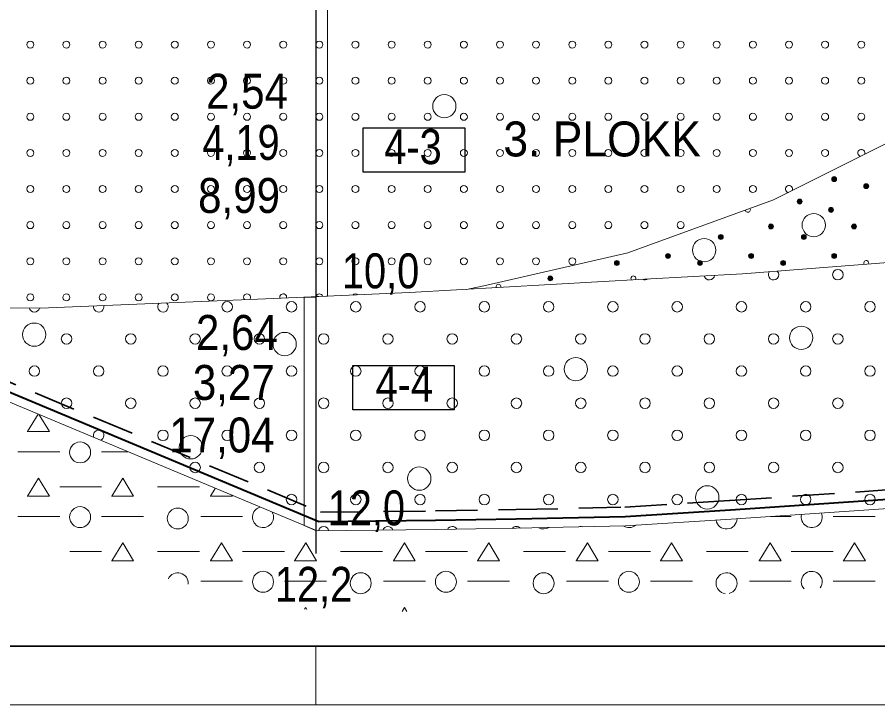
# Model space of a CAD drawing. Extents: x 640104 to 640970, y 6442278 to 6442689.
# Drawn here: x 640245.1 to 640319, y 6442488 to 6442547 of the extents above; entities that cross this region are included whole.
import ezdxf
from ezdxf.enums import TextEntityAlignment as Align

# ---------------------------------------------------------------- set-up
doc = ezdxf.new("R2010")
doc.units = 0
doc.header["$LTSCALE"] = 1.2
doc.linetypes.add('MEDIUM_DASHED', pattern=[4.5, 3, -1.5])
for name, color, linetype, lineweight in [('30', 7, 'Continuous', 13), ('31', 7, 'Continuous', 13), ('32', 7, 'Continuous', 25), ('33', 7, 'Continuous', 13), ('35', 7, 'Continuous', 35), ('42', 7, 'Continuous', 13), ('43', 7, 'Continuous', 13), ('44', 7, 'Continuous', 13), ('46', 7, 'Continuous', 13), ('47', 7, 'Continuous', 13)]:
    doc.layers.add(name, color=color, linetype=linetype, lineweight=lineweight)

msp = doc.modelspace()

# ---------------------------------------------------------------- hatches: boundary and pattern name
at = {"layer": '44'}
for points in [[(640315.439, 6442533.125, 1), (640315.019, 6442533.125, 1)], [(640318.187, 6442532.519, 1), (640317.767, 6442532.519, 1)], [(640312.473, 6442531.197, 1), (640312.053, 6442531.197, 1)], [(640315.165, 6442530.482, 1), (640314.745, 6442530.482, 1)], [(640310.01, 6442529.063, 1), (640309.59, 6442529.063, 1)], [(640317.143, 6442529.063, 1), (640316.723, 6442529.063, 1)], [(640305.704, 6442528.155, 1), (640305.284, 6442528.155, 1)], [(640312.837, 6442528.155, 1), (640312.417, 6442528.155, 1)], [(640301.173, 6442526.529, 1), (640300.753, 6442526.529, 1)], [(640308.306, 6442526.529, 1), (640307.886, 6442526.529, 1)], [(640315.439, 6442526.529, 1), (640315.019, 6442526.529, 1)], [(640296.788, 6442525.923, 1), (640296.368, 6442525.923, 1)], [(640303.921, 6442525.923, 1), (640303.501, 6442525.923, 1)], [(640311.054, 6442525.923, 1), (640310.634, 6442525.923, 1)], [(640291.074, 6442524.601, 1), (640290.654, 6442524.601, 1)]]:
    msp.add_hatch(color=256, dxfattribs=at).paths.add_polyline_path(points)

# ---------------------------------------------------------------- linework, layer by layer
at = {"layer": '30'}
msp.add_line((640270.76, 6442493), (640270.76, 6442488), dxfattribs=at)
at = {"layer": '31'}
for p, q in [((640107.01, 6442493.07), (640418.42, 6442493.07)), ((640107.01, 6442493), (640418.42, 6442493)), ((640107.01, 6442488), (640418.42, 6442488))]:
    msp.add_line(p, q, dxfattribs=at)
for points in [[(640283.68, 6442523.66), (640285.43, 6442524.03), (640297.52, 6442526.8), (640310.03, 6442531.34), (640323.29, 6442537.98), (640334.86, 6442544.42), (640343.76, 6442550.3), (640349.45, 6442554.85), (640357.08, 6442560.74), (640362.52, 6442565.74), (640369.51, 6442571.79), (640374.98, 6442577.56), (640379.02, 6442582.52), (640385.32, 6442590.78), (640390.41, 6442598.26), (640395.12, 6442604.77), (640397.49, 6442607.37), (640400.85, 6442610.03)], [(640224.72, 6442522.23), (640247.13, 6442522.05), (640267.13, 6442522.88), (640278.78, 6442523.38), (640298.96, 6442524.54), (640307.35, 6442525), (640322.43, 6442526.17), (640329.85, 6442527.49), (640338.89, 6442529.33), (640344.87, 6442530.55), (640353.66, 6442533.23), (640361.47, 6442536.65), (640368.18, 6442539.82), (640375.75, 6442544.7), (640385.64, 6442551.91), (640392.23, 6442556.06), (640395.16, 6442557.52), (640398.21, 6442558.74), (640401.26, 6442559.84), (640404.41, 6442560.91), (640412.75, 6442561.86), (640417.91, 6442562.22), (640418.42, 6442562.2)], [(640136.43, 6442546.57), (640165.21, 6442545.08), (640170.39, 6442544.98), (640270.85, 6442502.92), (640281.03, 6442503.04), (640287.95, 6442503.15), (640297.33, 6442503.37), (640306.38, 6442503.93), (640319.46, 6442504.83), (640339.78, 6442506.39), (640353.27, 6442507.39), (640379.6, 6442511.07), (640396.05, 6442513.09), (640404.66, 6442514), (640412.22, 6442514.76), (640418.42, 6442515.39)]]:
    msp.add_lwpolyline(points, dxfattribs=at)
at = {"layer": '32'}
msp.add_line((640270.76, 6442623), (640270.76, 6442501), dxfattribs=at)
at = {"layer": '33'}
for points in [[(640271.76, 6442523.08), (640271.76, 6442548), (640270.76, 6442548), (640270.76, 6442523.04)], [(640269.76, 6442522.99), (640269.76, 6442503.38), (640270.66, 6442503), (640270.76, 6442503), (640270.76, 6442523), (640269.93, 6442523)]]:
    msp.add_lwpolyline(points, close=True, dxfattribs=at)
at = {"layer": '33', "lineweight": 25}
for points in [[(640274.82, 6442537.53), (640283.53, 6442537.53), (640283.53, 6442533.73), (640274.82, 6442533.73)], [(640273.92, 6442517.13), (640282.63, 6442517.13), (640282.63, 6442513.33), (640273.92, 6442513.33)]]:
    msp.add_lwpolyline(points, close=True, dxfattribs=at)
at = {"layer": '35', "linetype": 'MEDIUM_DASHED'}
msp.add_lwpolyline([(640171.96, 6442546.06), (640271.16, 6442504.53), (640281.01, 6442504.64), (640287.92, 6442504.75), (640297.26, 6442504.97), (640306.27, 6442505.53), (640319.35, 6442506.42), (640339.66, 6442507.99), (640353.1, 6442508.98), (640379.39, 6442512.65), (640395.87, 6442514.68), (640403.06, 6442515.44)], dxfattribs=at)
at = {"layer": '35', "lineweight": 40}
msp.add_lwpolyline([(640171.16, 6442545.53), (640271, 6442503.73), (640281.02, 6442503.84), (640287.94, 6442503.95), (640297.3, 6442504.17), (640306.32, 6442504.73), (640319.41, 6442505.62), (640339.72, 6442507.19), (640353.18, 6442508.19), (640379.49, 6442511.86), (640395.96, 6442513.88), (640403.86, 6442514.72)], dxfattribs=at)
at = {"layer": '42'}
for centre in [(640315.544, 6442524.92), (640263.147, 6442522.162), (640268.663, 6442522.162), (640274.178, 6442522.162), (640279.693, 6442522.162), (640285.209, 6442522.162), (640290.724, 6442522.162), (640296.24, 6442522.162), (640301.755, 6442522.162), (640307.271, 6442522.162), (640312.786, 6442522.162), (640318.301, 6442522.162), (640249.359, 6442519.404), (640254.874, 6442519.404), (640260.389, 6442519.404), (640265.905, 6442519.404), (640271.42, 6442519.404), (640276.936, 6442519.404), (640282.451, 6442519.404), (640287.967, 6442519.404), (640293.482, 6442519.404), (640298.997, 6442519.404), (640304.513, 6442519.404), (640310.028, 6442519.404), (640315.544, 6442519.404), (640246.601, 6442516.647), (640252.116, 6442516.647), (640257.632, 6442516.647), (640263.147, 6442516.647), (640268.663, 6442516.647), (640274.178, 6442516.647), (640279.693, 6442516.647), (640285.209, 6442516.647), (640290.724, 6442516.647), (640296.24, 6442516.647), (640301.755, 6442516.647), (640307.271, 6442516.647), (640312.786, 6442516.647), (640318.301, 6442516.647), (640249.359, 6442513.889), (640254.874, 6442513.889), (640260.389, 6442513.889), (640265.905, 6442513.889), (640271.42, 6442513.889), (640276.936, 6442513.889), (640282.451, 6442513.889), (640287.967, 6442513.889), (640293.482, 6442513.889), (640298.997, 6442513.889), (640304.513, 6442513.889), (640310.028, 6442513.889), (640315.544, 6442513.889), (640257.632, 6442511.131), (640263.147, 6442511.131), (640268.663, 6442511.131), (640274.178, 6442511.131), (640279.693, 6442511.131), (640285.209, 6442511.131), (640290.724, 6442511.131), (640296.24, 6442511.131), (640301.755, 6442511.131), (640307.271, 6442511.131), (640312.786, 6442511.131), (640318.301, 6442511.131), (640260.389, 6442508.374), (640265.905, 6442508.374), (640271.42, 6442508.374), (640276.936, 6442508.374), (640282.451, 6442508.374), (640287.967, 6442508.374), (640293.482, 6442508.374), (640298.997, 6442508.374), (640304.513, 6442508.374), (640310.028, 6442508.374), (640315.544, 6442508.374), (640268.663, 6442505.616), (640274.178, 6442505.616), (640279.693, 6442505.616), (640285.209, 6442505.616), (640290.724, 6442505.616), (640296.24, 6442505.616), (640301.755, 6442505.616), (640307.271, 6442505.616), (640312.786, 6442505.616), (640318.301, 6442505.616)]:
    msp.add_circle(centre, 0.45, dxfattribs=at)
for centre, start, end in [((640310.028, 6442524.92), 144.28306, 44.54039), ((640298.997, 6442524.92), 239.27292, 307.13568), ((640304.513, 6442524.92), 192.23369, 354.04276), ((640246.601, 6442522.162), 193.37807, 345.67679), ((640252.116, 6442522.162), 170.14064, 14.62174), ((640257.632, 6442522.162), 136.22376, 48.53863), ((640252.116, 6442511.131), 288.70447, 205.86033), ((640271.42, 6442502.858), 9.85513, 171.43858), ((640276.936, 6442502.858), 18.00801, 163.2857), ((640282.451, 6442502.858), 27.79631, 154.05178), ((640287.967, 6442502.858), 41.88958, 140.40784), ((640293.482, 6442502.858), 71.67364, 111.05422)]:
    msp.add_arc(centre, 0.45, start, end, dxfattribs=at)
at = {"layer": '43'}
for centre in [(640246.249, 6442544.673), (640249.349, 6442544.673), (640252.449, 6442544.673), (640255.549, 6442544.673), (640258.649, 6442544.673), (640261.749, 6442544.673), (640264.849, 6442544.673), (640267.949, 6442544.673), (640271.049, 6442544.673), (640274.149, 6442544.673), (640277.249, 6442544.673), (640280.349, 6442544.673), (640283.449, 6442544.673), (640286.549, 6442544.673), (640289.649, 6442544.673), (640292.749, 6442544.673), (640295.849, 6442544.673), (640298.949, 6442544.673), (640302.049, 6442544.673), (640305.149, 6442544.673), (640308.249, 6442544.673), (640311.349, 6442544.673), (640314.449, 6442544.673), (640317.549, 6442544.673), (640246.249, 6442541.573), (640249.349, 6442541.573), (640252.449, 6442541.573), (640255.549, 6442541.573), (640258.649, 6442541.573), (640261.749, 6442541.573), (640264.849, 6442541.573), (640267.949, 6442541.573), (640271.049, 6442541.573), (640274.149, 6442541.573), (640277.249, 6442541.573), (640280.349, 6442541.573), (640283.449, 6442541.573), (640286.549, 6442541.573), (640289.649, 6442541.573), (640292.749, 6442541.573), (640295.849, 6442541.573), (640298.949, 6442541.573), (640302.049, 6442541.573), (640305.149, 6442541.573), (640308.249, 6442541.573), (640311.349, 6442541.573), (640314.449, 6442541.573), (640317.549, 6442541.573), (640246.249, 6442538.473), (640249.349, 6442538.473), (640252.449, 6442538.473), (640255.549, 6442538.473), (640258.649, 6442538.473), (640261.749, 6442538.473), (640264.849, 6442538.473), (640267.949, 6442538.473), (640271.049, 6442538.473), (640274.149, 6442538.473), (640277.249, 6442538.473), (640280.349, 6442538.473), (640283.449, 6442538.473), (640286.549, 6442538.473), (640289.649, 6442538.473), (640292.749, 6442538.473), (640295.849, 6442538.473), (640298.949, 6442538.473), (640302.049, 6442538.473), (640305.149, 6442538.473), (640308.249, 6442538.473), (640311.349, 6442538.473), (640314.449, 6442538.473), (640317.549, 6442538.473), (640246.249, 6442535.373), (640249.349, 6442535.373), (640252.449, 6442535.373), (640255.549, 6442535.373), (640258.649, 6442535.373), (640261.749, 6442535.373), (640264.849, 6442535.373), (640267.949, 6442535.373), (640271.049, 6442535.373), (640274.149, 6442535.373), (640277.249, 6442535.373), (640280.349, 6442535.373), (640283.449, 6442535.373), (640286.549, 6442535.373), (640289.649, 6442535.373), (640292.749, 6442535.373), (640295.849, 6442535.373), (640298.949, 6442535.373), (640302.049, 6442535.373), (640305.149, 6442535.373), (640308.249, 6442535.373), (640311.349, 6442535.373), (640314.449, 6442535.373), (640246.249, 6442532.273), (640249.349, 6442532.273), (640252.449, 6442532.273), (640255.549, 6442532.273), (640258.649, 6442532.273), (640261.749, 6442532.273), (640264.849, 6442532.273), (640267.949, 6442532.273), (640271.049, 6442532.273), (640274.149, 6442532.273), (640277.249, 6442532.273), (640280.349, 6442532.273), (640283.449, 6442532.273), (640286.549, 6442532.273), (640289.649, 6442532.273), (640292.749, 6442532.273), (640295.849, 6442532.273), (640298.949, 6442532.273), (640302.049, 6442532.273), (640305.149, 6442532.273), (640308.249, 6442532.273), (640246.249, 6442529.173), (640249.349, 6442529.173), (640252.449, 6442529.173), (640255.549, 6442529.173), (640258.649, 6442529.173), (640261.749, 6442529.173), (640264.849, 6442529.173), (640267.949, 6442529.173), (640271.049, 6442529.173), (640274.149, 6442529.173), (640277.249, 6442529.173), (640280.349, 6442529.173), (640283.449, 6442529.173), (640286.549, 6442529.173), (640289.649, 6442529.173), (640292.749, 6442529.173), (640295.849, 6442529.173), (640298.949, 6442529.173), (640302.049, 6442529.173), (640246.249, 6442526.073), (640249.349, 6442526.073), (640252.449, 6442526.073), (640255.549, 6442526.073), (640258.649, 6442526.073), (640261.749, 6442526.073), (640264.849, 6442526.073), (640267.949, 6442526.073), (640271.049, 6442526.073), (640274.149, 6442526.073), (640277.249, 6442526.073), (640280.349, 6442526.073), (640283.449, 6442526.073), (640286.549, 6442526.073), (640289.649, 6442526.073), (640292.749, 6442526.073), (640246.249, 6442522.973), (640249.349, 6442522.973), (640252.449, 6442522.973), (640255.549, 6442522.973), (640258.649, 6442522.973), (640261.749, 6442522.973)]:
    msp.add_circle(centre, 0.3, dxfattribs=at)
for centre, start, end in [((640317.549, 6442535.373), 333.52941, 259.60069), ((640311.349, 6442532.273), 333.52941, 259.60069), ((640264.849, 6442522.973), 324.16538, 220.597), ((640267.949, 6442522.973), 351.67862, 193.19468), ((640271.049, 6442522.973), 17.07144, 167.80185), ((640274.149, 6442522.973), 46.22336, 138.64994)]:
    msp.add_arc(centre, 0.3, start, end, dxfattribs=at)
at = {"layer": '44'}
for centre in [(640315.229, 6442533.125), (640317.977, 6442532.519), (640312.263, 6442531.197), (640314.955, 6442530.482), (640309.8, 6442529.063), (640316.933, 6442529.063), (640305.494, 6442528.155), (640312.627, 6442528.155), (640300.963, 6442526.529), (640308.096, 6442526.529), (640315.229, 6442526.529), (640296.578, 6442525.923), (640303.711, 6442525.923), (640310.844, 6442525.923), (640290.864, 6442524.601)]:
    msp.add_circle(centre, 0.21, dxfattribs=at)
for centre, start, end in [((640307.822, 6442530.482), 184.23112, 35.7351), ((640317.977, 6442525.923), 336.24488, 212.57856), ((640297.997, 6442524.601), 330.86934, 215.74711), ((640286.423, 6442523.886), 345.01586, 201.60058)]:
    msp.add_arc(centre, 0.21, start, end, dxfattribs=at)
at = {"layer": '46'}
for p, q in [((640248.77, 6442509.72), (640245.17, 6442509.72)), ((640254.63, 6442509.71), (640252.37, 6442509.71)), ((640252.37, 6442506.72), (640248.77, 6442506.72)), ((640260.77, 6442506.72), (640257.17, 6442506.72)), ((640248.77, 6442504.16), (640245.17, 6442504.16)), ((640255.97, 6442504.16), (640252.37, 6442504.16)), ((640264.47, 6442504.16), (640260.87, 6442504.16)), ((640311.55, 6442504.16), (640309.76, 6442504.16)), ((640318.75, 6442504.16), (640315.15, 6442504.16)), ((640252.37, 6442501.16), (640249.65, 6442501.16)), ((640260.77, 6442501.17), (640257.17, 6442501.17)), ((640268.07, 6442501.16), (640264.47, 6442501.16)), ((640276.47, 6442501.17), (640272.87, 6442501.17)), ((640283.76, 6442501.16), (640280.16, 6442501.16)), ((640292.16, 6442501.17), (640288.56, 6442501.17)), ((640299.46, 6442501.16), (640295.86, 6442501.16)), ((640307.86, 6442501.17), (640304.26, 6442501.17)), ((640315.15, 6442501.16), (640311.55, 6442501.16)), ((640264.47, 6442498.61), (640260.87, 6442498.61)), ((640271.67, 6442498.6), (640268.07, 6442498.6)), ((640280.16, 6442498.61), (640276.56, 6442498.61)), ((640287.36, 6442498.6), (640283.76, 6442498.6)), ((640295.86, 6442498.61), (640292.26, 6442498.61)), ((640303.06, 6442498.6), (640299.46, 6442498.6)), ((640311.55, 6442498.61), (640307.95, 6442498.61)), ((640318.75, 6442498.6), (640315.15, 6442498.6))]:
    msp.add_line(p, q, dxfattribs=at)
for points in [[(640246.01, 6442511.44), (640246.02, 6442511.47), (640246.93, 6442512.94)], [(640247.02, 6442512.9), (640247.89, 6442511.46), (640246.09, 6442511.47)], [(640246.01, 6442505.89), (640246.02, 6442505.91), (640246.96, 6442507.44), (640247.89, 6442505.9), (640246.09, 6442505.91)], [(640253.23, 6442505.89), (640253.24, 6442505.91), (640254.18, 6442507.44), (640255.11, 6442505.9), (640253.31, 6442505.91)], [(640261.71, 6442505.89), (640261.71, 6442505.91), (640262.12, 6442506.58)], [(640263.54, 6442505.98), (640263.59, 6442505.9), (640261.79, 6442505.91)], [(640253.23, 6442500.34), (640253.24, 6442500.36), (640254.18, 6442501.89), (640255.11, 6442500.35), (640253.31, 6442500.36)], [(640261.71, 6442500.34), (640261.71, 6442500.36), (640262.66, 6442501.89), (640263.59, 6442500.35), (640261.79, 6442500.36)], [(640268.93, 6442500.34), (640268.93, 6442500.36), (640269.88, 6442501.89), (640270.81, 6442500.35), (640269.01, 6442500.36)], [(640277.4, 6442500.34), (640277.41, 6442500.36), (640278.35, 6442501.89), (640279.28, 6442500.35), (640277.48, 6442500.36)], [(640284.62, 6442500.34), (640284.63, 6442500.36), (640285.58, 6442501.89), (640286.51, 6442500.35), (640284.71, 6442500.36)], [(640293.1, 6442500.34), (640293.1, 6442500.36), (640294.05, 6442501.89), (640294.98, 6442500.35), (640293.18, 6442500.36)], [(640300.32, 6442500.34), (640300.32, 6442500.36), (640301.27, 6442501.89), (640302.2, 6442500.35), (640300.4, 6442500.36)], [(640308.79, 6442500.34), (640308.8, 6442500.36), (640309.74, 6442501.89), (640310.67, 6442500.35), (640308.87, 6442500.36)], [(640316.01, 6442500.34), (640316.02, 6442500.36), (640316.97, 6442501.89), (640317.9, 6442500.35), (640316.1, 6442500.36)], [(640269.79, 6442496.2), (640269.88, 6442496.34), (640269.97, 6442496.19)], [(640278.16, 6442496.02), (640278.35, 6442496.34), (640278.55, 6442496.02)]]:
    msp.add_lwpolyline(points, dxfattribs=at)
for centre in [(640250.522, 6442509.666), (640250.522, 6442504.112), (640258.904, 6442503.99), (640266.217, 6442498.557), (640274.6, 6442498.435), (640281.913, 6442498.557), (640290.295, 6442498.435), (640297.608, 6442498.557)]:
    msp.add_circle(centre, 0.9, dxfattribs=at)
for centre, start, end in [((640266.217, 6442504.112), 107.05843, 27.50637), ((640313.303, 6442504.112), 164.90478, 22.92027), ((640305.99, 6442503.99), 188.72547, 358.55764), ((640290.295, 6442503.99), 241.87334, 300.85451), ((640297.608, 6442504.112), 235.72643, 310.42077), ((640258.904, 6442498.435), 355.4537, 154.23817), ((640305.99, 6442498.435), 285.01729, 261.75538), ((640313.303, 6442498.557), 323.96653, 222.80614)]:
    msp.add_arc(centre, 0.9, start, end, dxfattribs=at)
at = {"layer": '47'}
for centre in [(640281.775, 6442539.382), (640313.473, 6442529.174), (640304.071, 6442527.025), (640246.584, 6442519.772), (640312.398, 6442519.504), (640268.074, 6442518.966), (640293.057, 6442516.817), (640260.016, 6442510.102), (640279.626, 6442507.415), (640304.339, 6442505.804)]:
    msp.add_circle(centre, 1, dxfattribs=at)

# ---------------------------------------------------------------- texts
at = {"layer": '32', "width": 0.85}
for s, p in [('10,0', (640276.305, 6442523.75)), ('12,0', (640275.085, 6442503.4)), ('12,2', (640270.55, 6442496.84))]:
    msp.add_text(s, height=3, dxfattribs=at).set_placement(p, align=Align.CENTER)
at = {"layer": '33'}
for s, width, p in [('2,54', 0.9, (640264.845, 6442539.17)), ('4,19', 0.85, (640264.325, 6442534.77)), ('4-3', 0.85, (640279.085, 6442534.41)), ('8,99', 0.9, (640264.16, 6442530.22)), ('2,64', 0.9, (640263.975, 6442518.46)), ('3,27', 0.9, (640263.71, 6442514.17)), ('4-4', 0.85, (640278.34, 6442514.03)), ('17,04', 0.9, (640262.69, 6442509.66))]:
    msp.add_text(s, height=3, dxfattribs=dict(at, width=width)).set_placement(p, align=Align.CENTER)
at = {"layer": '35', "width": 0.95}
msp.add_text('3. PLOKK', height=3, dxfattribs=at).set_placement((640295.315, 6442535.07), align=Align.CENTER)

doc.saveas('drawing.dxf')
